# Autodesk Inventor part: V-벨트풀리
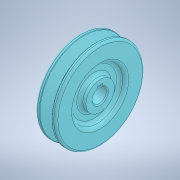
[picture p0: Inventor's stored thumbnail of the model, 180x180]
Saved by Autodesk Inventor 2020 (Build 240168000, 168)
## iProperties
Created: 2024-04
Part Number: V-벨트풀리
Material: 일반
Document SubType Name: Modeling
Designer: oem
Density: 1 g/cm^3
Appearance: 기본값
Author: jhkim
Sending System: Autodesk Inventor 2025
Preprocessor: ST-DEVELOPER v20
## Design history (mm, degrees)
feature "솔리드1"
node "솔리드2"
